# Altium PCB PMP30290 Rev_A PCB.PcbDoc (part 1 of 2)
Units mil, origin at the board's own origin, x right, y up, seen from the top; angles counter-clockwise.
Board outline 2460 x 2050 mil, 4 copper layers (Top Layer, Inner Layer 1, Inner Layer 2, Bottom Layer), stack 84.834 mil thick; 95 components, 59 nets, 283 pads, 121 vias.
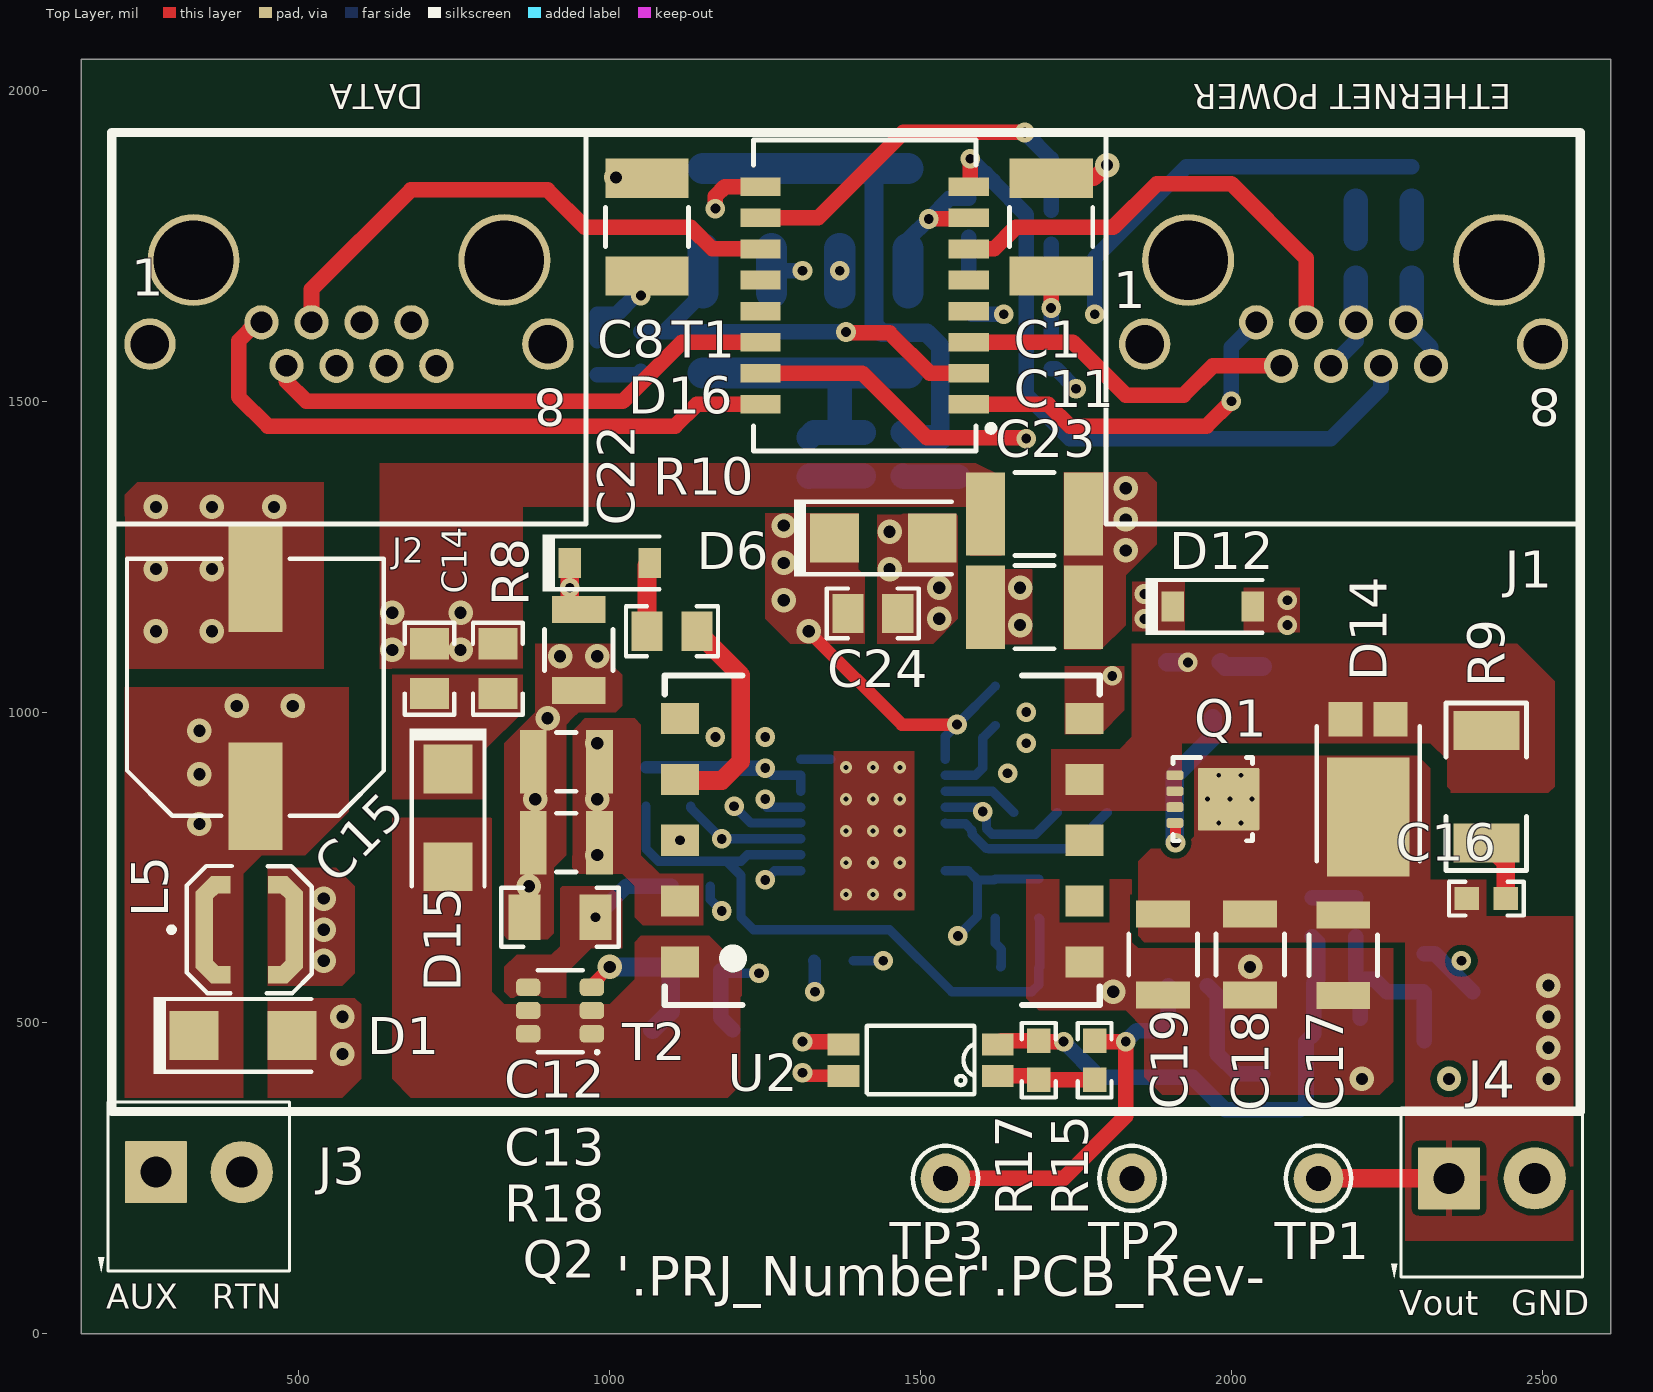
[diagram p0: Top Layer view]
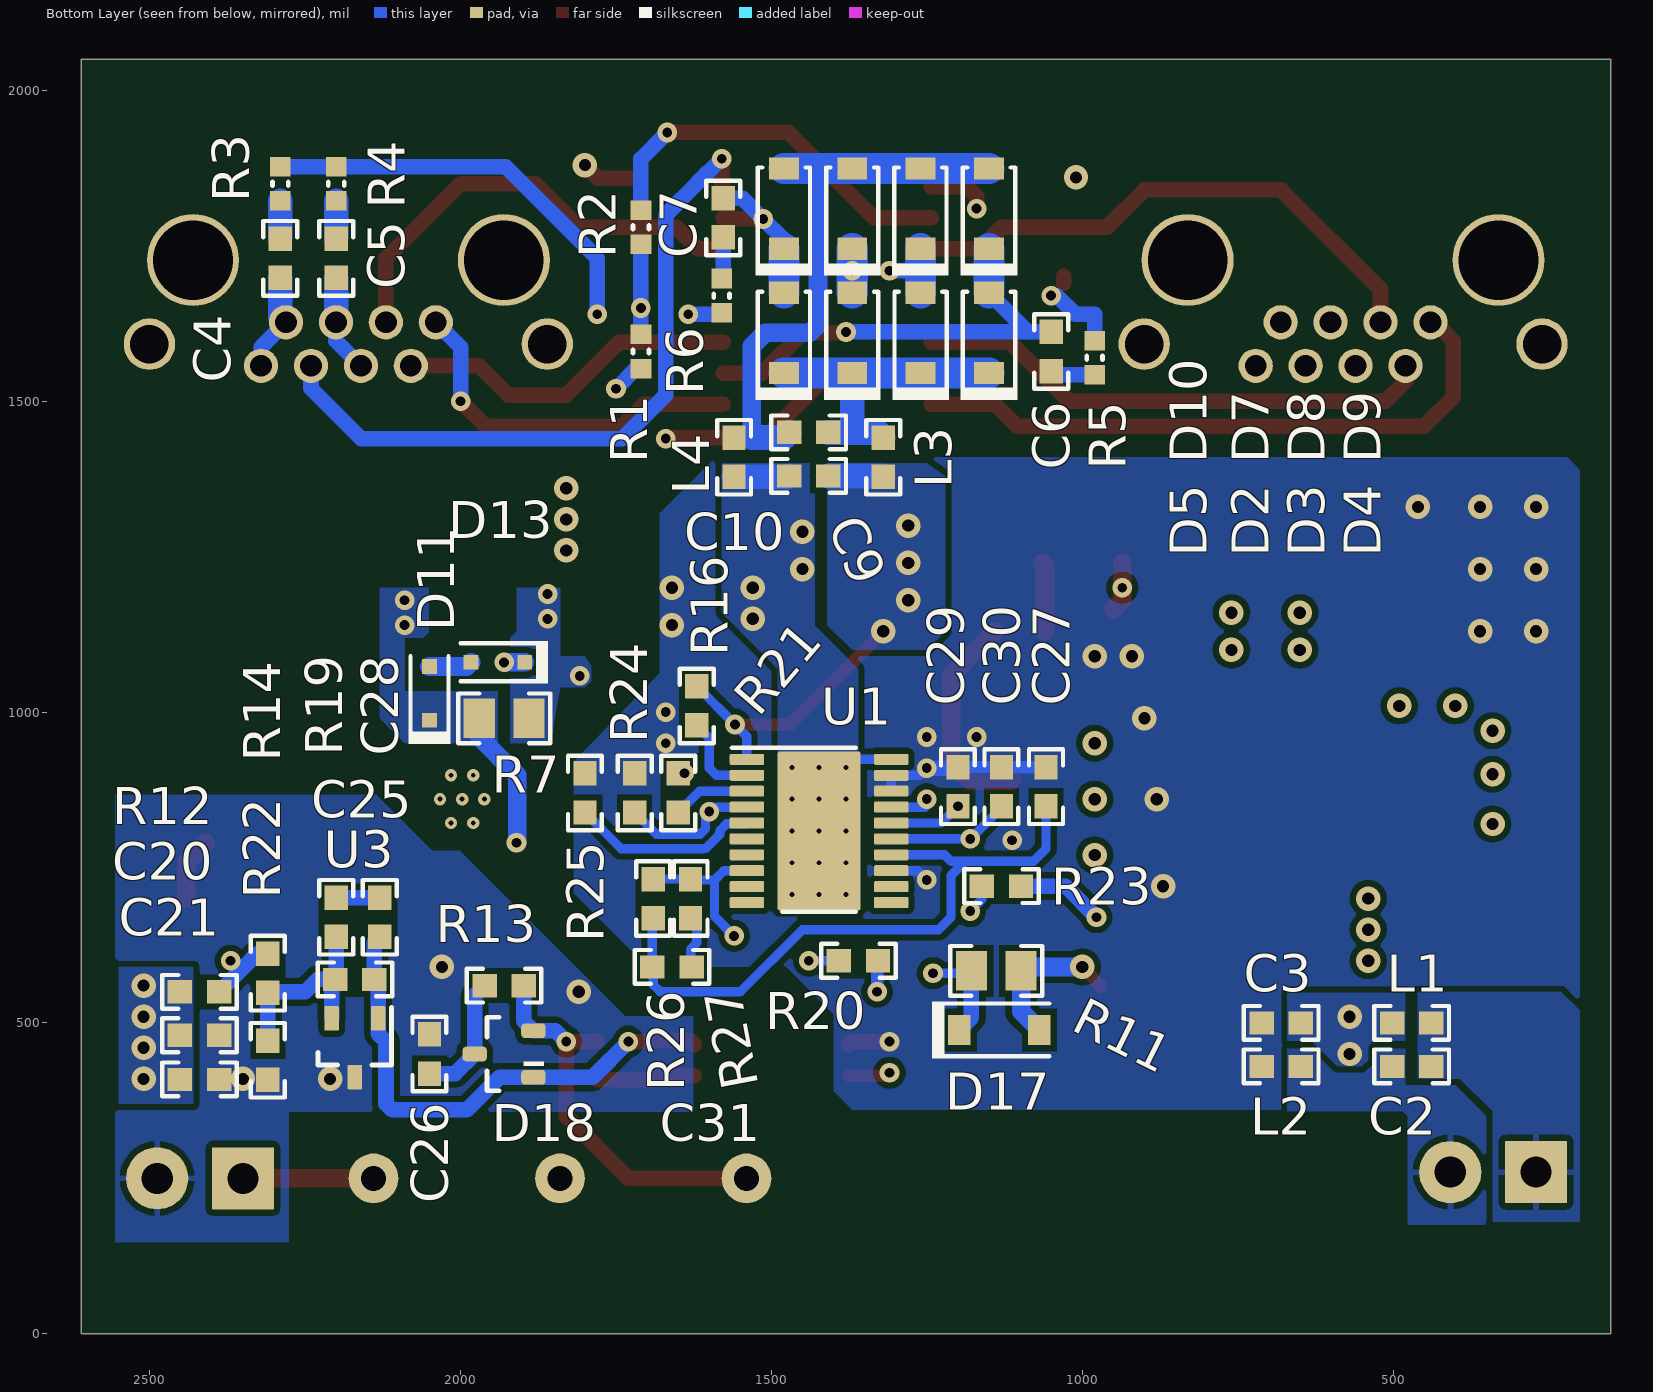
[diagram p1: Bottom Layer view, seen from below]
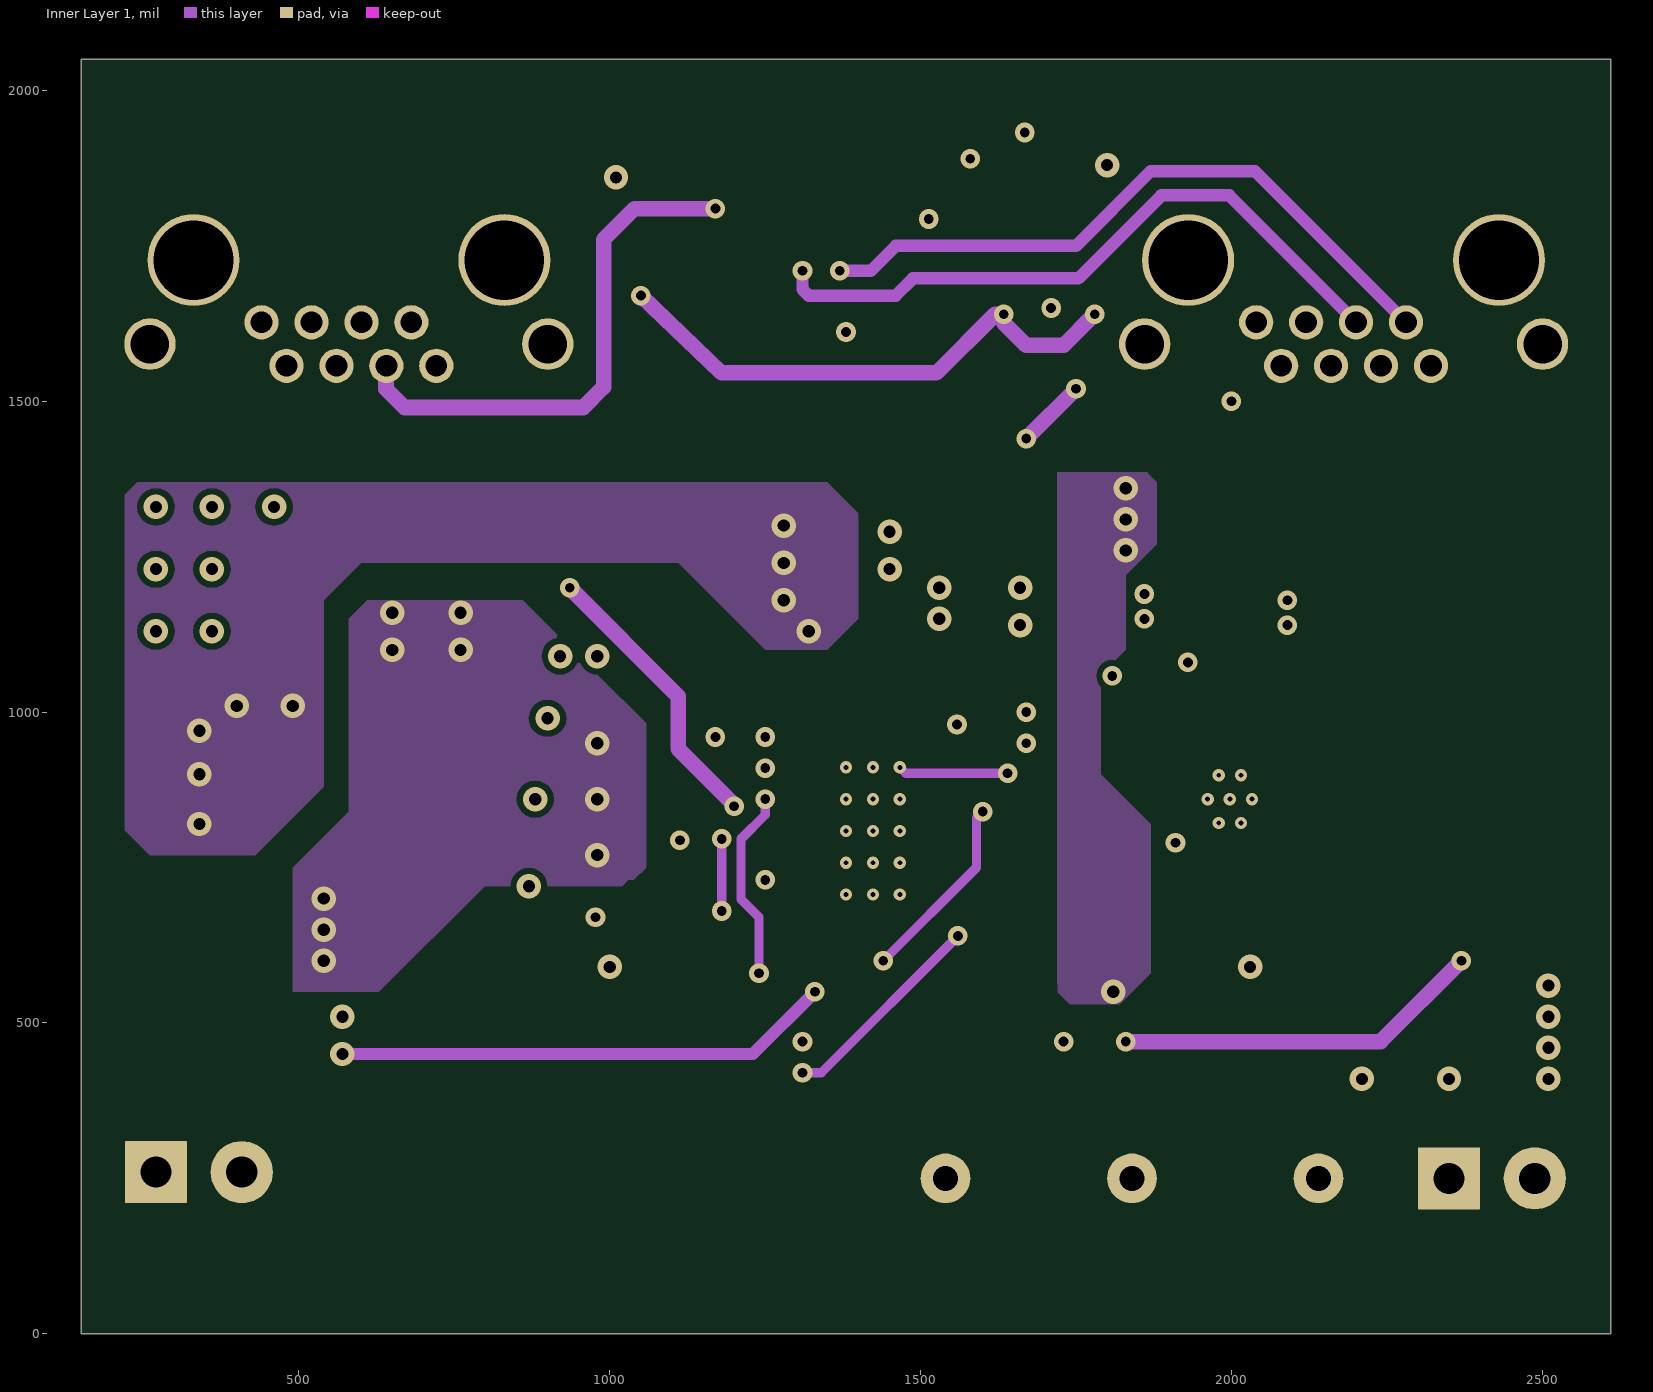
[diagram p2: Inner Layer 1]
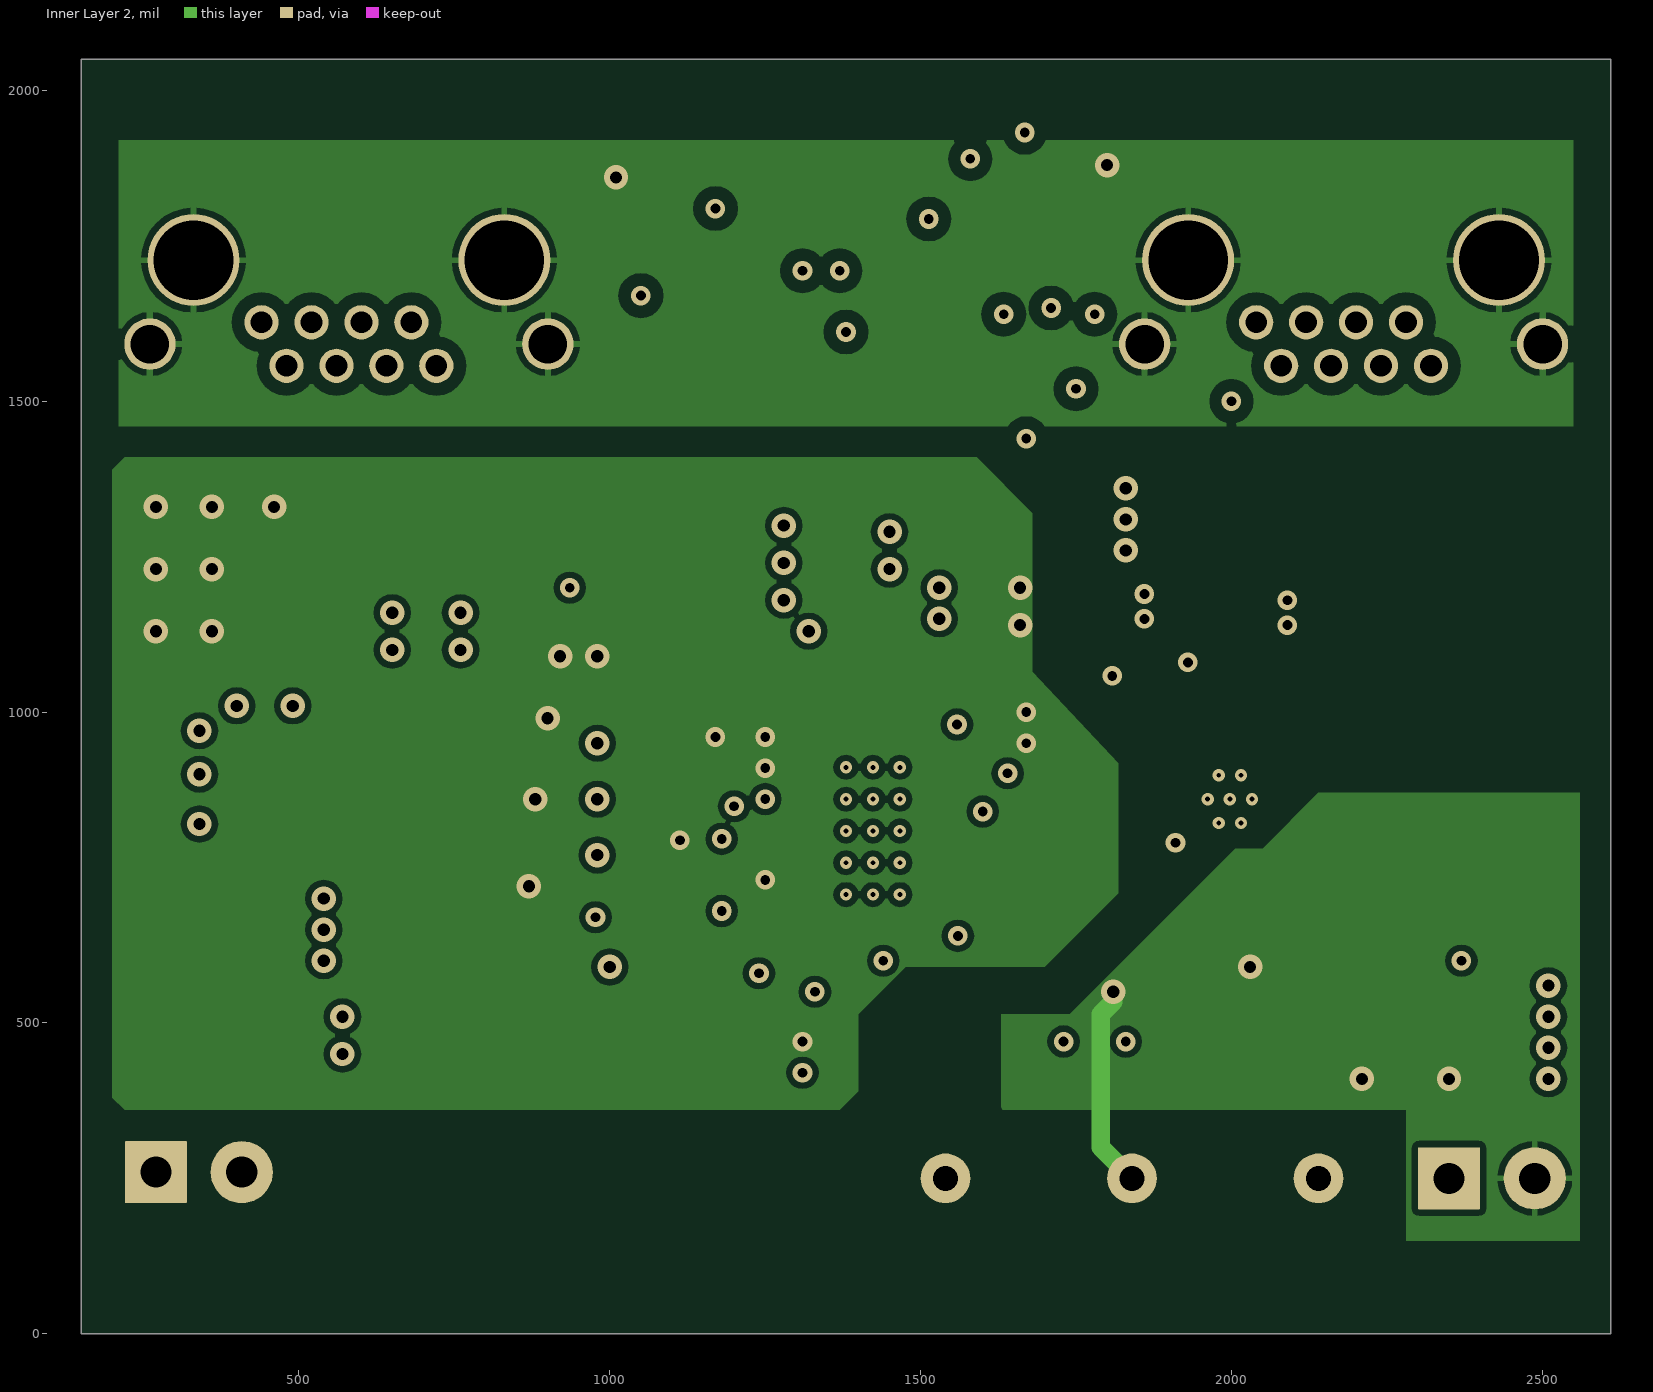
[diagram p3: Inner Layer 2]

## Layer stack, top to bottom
Top Solder: solder mask 0.4, Solder Resist, Dk 3.5
Top Layer: signal copper 1.4
Dielectric 3: dielectric 10, Dk 4.2
Inner Layer 1: signal copper 1.417
Dielectric1: core 59.2, FR-4, Dk 4.8
Inner Layer 2: signal copper 1.417
Dielectric 2: dielectric 10, Dk 4.2
Bottom Layer: signal copper 1.4
Bottom Solder: solder mask 0.4, Solder Resist, Dk 3.5

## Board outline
150,0 150,2050 2610,2050 2610,0

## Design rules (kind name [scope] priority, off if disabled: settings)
AcuteAngle [All] p1: minimum=4.50000000000000E+0001 checktracksonly=FALSE
AssemblyTestPointUsage [All] p1: valid=2
BoardOutlineClearance BoardOutlineClearance_MountingHoles [OnCopper and InComponentClass('Mounting Holes')] p1: gap=40
BoardOutlineClearance BoardOutlineClearance_Poly [OnCopper and IsPoly] p2: gap=25
BoardOutlineClearance [OnCopper and Not InComponentClass('Logo') and not InComponentClass('FiducialMark') and not InRegion(1000,500,4000,800) and not InPoly] p3: gap=75
Clearance "Schematic Clearance Constraint" [InNet('BSP')] p1: gap=20
Clearance Clearance_Keepouts [((IsTrack Or IsArc) And Not InPoly) And IsFree and IsKeepOut vs ((IsTrack Or IsArc) And Not InPoly) And IsFree and IsKeepOut] p2: gap=0
Clearance Clearance_Poly [InPolygon] p3: gap=10
Clearance [All] p4: gap=7.87
ComponentClearance ComponentClearance_MountingHoles_FiducialMarks [InComponentClass('Mounting Holes') vs InComponentClass('FiducialMark')] p1: gap=50 collisioncheckmode=3 verticalgap=10 showdistances=FALSE
ComponentClearance ComponentClearance_Shunt [InComponentClass('Header') vs InComponentClass('Shunt')] p2: gap=0 collisioncheckmode=3 verticalgap=0 showdistances=FALSE
ComponentClearance ComponentClearance_Logo [InComponentClass('Logo')] p3: gap=50 collisioncheckmode=3 verticalgap=10 showdistances=FALSE
ComponentClearance ComponentClearance_ScrewToNut [(HasFootprint('NY PMS 440 0025 PH')) vs (HasFootprint('Keystone_1902C'))] p4: gap=5 collisioncheckmode=3 verticalgap=10 showdistances=FALSE
ComponentClearance ComponentClearance_MountingHoles [InComponentClass('Mounting Holes')] p5: gap=250 collisioncheckmode=3 verticalgap=100000 showdistances=FALSE
ComponentClearance ComponentClearance_SmallPassives [HasFootprint('0201*') or HasFootprint('0402*') or HasFootprint('0508') or HasFootprint('0603*') or HasFootprint('0612') or HasFootprint('0805*') or HasFootprint('0815*') or HasFootprint('0830*') or HasFootprint('1206*') or HasFootprint('1210*') or HasFootprint('1808*') or HasFootprint('1812*') or HasFootprint('1825*') or HasFootprint('2010*') or HasFootprint('2220*') or HasFootprint('2225*') or HasFootprint('2512*') or HasFootprint('2728*') or HasFootprint('3518*') vs HasFootprint('0201*') or HasFootprint('0402*') or HasFootprint('0508') or HasFootprint('0603*') or HasFootprint('0612') or HasFootprint('0805*') or HasFootprint('0815*') or HasFootprint('0830*') or HasFootprint('1206*') or HasFootprint('1210*') or HasFootprint('1808*') or HasFootprint('1812*') or HasFootprint('1825*') or HasFootprint('2010*') or HasFootprint('2220*') or HasFootprint('2225*') or HasFootprint('2512*') or HasFootprint('2728*') or HasFootprint('3518*')] p6: gap=14.96 collisioncheckmode=3 verticalgap=10 showdistances=FALSE
ComponentClearance ComponentClearance_THtoSMT [IsThruComponent vs IsSMTComponent] p7: gap=40 collisioncheckmode=3 verticalgap=30 showdistances=FALSE
ComponentClearance ComponentClearance_THtoTH [IsThruComponent vs IsThruComponent] p8: gap=30 collisioncheckmode=3 verticalgap=30 showdistances=FALSE
ComponentClearance [All] p9: gap=30 collisioncheckmode=3 verticalgap=10 showdistances=FALSE
DiffPairsRouting [All] p1: maxlimit=100 minlimit=10 mostfreqgap=10 toplayer_minwidth=15 toplayer_maxwidth=15 toplayer_prefwidth=15 midlayer1_minwidth=15 midlayer1_maxwidth=15 midlayer1_prefwidth=15 midlayer2_minwidth=15 midlayer2_maxwidth=15 midlayer2_prefwidth=15 bottomlayer_minwidth=15 bottomlayer_maxwidth=15 bottomlayer_prefwidth=15 maxuncoupledlength=1000
FabricationTestPointUsage TestPointUsage [All] p1: valid=2 allowmultiple=FALSE
FabricationTestpoint Testpoint [All] p1: side=3 testpointundercomponent=TRUE minsize=40 maxsize=100 preferedsize=60 minholesize=0 maxholesize=40 preferedholesize=32 testpointgrid=1 allowsidetop=TRUE allowsidebottom=TRUE usegrid=TRUE gridtolerance=0.01
FanoutControl Fanout_LCC [IsLCC] p1: bgadir=Out bgaviamode=Centered fanoutstyle=Auto fanoutdirection=Alternating viagrid=1 // Fanout_LCC (Default Rule)
FanoutControl Fanout_BGA [IsBGA] p2: bgadir=Out bgaviamode=Centered fanoutstyle=Auto fanoutdirection=Alternating viagrid=1 // Fanout_BGA (Default Rule)
FanoutControl Fanout_Default [All] p4: bgadir=Out bgaviamode=Centered fanoutstyle=Auto fanoutdirection=Alternating viagrid=1 // Fanout_Default (Default Rule)
FanoutControl Fanout_Small [(CompPinCount < 5)] p5: bgadir=Out bgaviamode=Centered fanoutstyle=Auto fanoutdirection=OutThenIn viagrid=1 // Fanout_Small (Default Rule)
HoleSize [All] p1: absolutevalues=TRUE maxlimit=251 minlimit=7.87 maxpercent=80.000 minpercent=20.000
MinimumAnnularRing MinimumAnnularRing_ThermalPadVias [IsVia and InAnyComponent] p1: minimumring=5.91
MinimumAnnularRing [All] p2: minimumring=8
MinimumSolderMaskSliver MinimumSolderMaskSliver_Logo [InComponentClass('Logo') vs InComponentClass('Logo')] p1: minsoldermaskwidth=0.7
MinimumSolderMaskSliver [All] p2: minsoldermaskwidth=3.94
PlaneConnect [All] p1: planeconnectstyle=Relief reliefexpansion=10 reliefentries=4 reliefconductorwidth=10 reliefairgap=10
PolygonConnect PolygonConnect_2 [All vs IsSMTPin] p1: connectstyle=Direct reliefconductorwidth=10 reliefentries=4 polygonreliefangle="90 Angle" airgapwidth=10
PolygonConnect PolygonConnect_3 [All vs IsVia] p2: connectstyle=Direct reliefconductorwidth=10 reliefentries=4 polygonreliefangle="90 Angle" airgapwidth=10
PolygonConnect PolygonConnect_1 [All vs IsNamedPolygon('BSP')] p3: connectstyle=Relief reliefconductorwidth=10 reliefentries=4 polygonreliefangle="90 Angle" airgapwidth=10
PolygonConnect [All] p4: connectstyle=Relief reliefconductorwidth=10 reliefentries=4 polygonreliefangle="90 Angle" airgapwidth=10
RoomDefinition "PMP30290 RevA Schematic Page 2" [InComponentClass('PMP30290 RevA Schematic Page 2')] p1: confinementstyle=ConfineIn formatcopy=TRUE lockcomponents=FALSE outline -692,-1534 1308,-1534 1308,-534 -692,-534
RoomDefinition "PMP30290 RevA Schematic Page 1" [InComponentClass('PMP30290 RevA Schematic Page 1')] p2: confinementstyle=ConfineIn formatcopy=TRUE lockcomponents=FALSE outline -692,-1534 1308,-1534 1308,-534 -692,-534
RoutingVias ThermalPadVias [IsVia and InAnyComponent] p1: holewidth=7.87 width=19.68 viastyle="Through Hole" minholewidth=7.87 minwidth=19.68 maxholewidth=12.99 maxwidth=23.62
RoutingVias [All] p2: holewidth=16 width=34 viastyle="Through Hole" minholewidth=7.87 minwidth=26 maxholewidth=40 maxwidth=65 useviatemplates=TRUE viatemplateguid#1={23C83835-86FD-4572-BB9E-8314481B5725} viatemplatename#1=v80h40
SilkToBoardRegionClearance [Not ((IsComment or IsDesignator) And (Hide <> 'False')) and not InRegion(1000,500,4000,800)] p1:
SilkToSilkClearance SilkToSilkClearance_Pb-FreeLogo [(HasFootprint('Pb-Free_Overlay_Medium') OR HasFootprint('Pb-Free_Overlay_Small')) vs (HasFootprint('Pb-Free_Overlay_Medium') OR HasFootprint('Pb-Free_Overlay_Small'))] p1: silktosilkclearance=0
SilkToSilkClearance [All] p2: silktosilkclearance=4
SilkToSolderMaskClearance SilkToComponentPadClearance [(IsPad or IsFill or IsRegion) and InAnycomponent] p1: minsilkscreentomaskgap=5 clearancetoexposedcopper=TRUE
SilkToSolderMaskClearance "Silk to Solder Mask Opening" [All] p2: minsilkscreentomaskgap=4 clearancetoexposedcopper=FALSE
SolderMaskExpansion [All] p1: expansion=1.97
Width [All] p1: maxlimit=100 minlimit=6 preferedwidth=10 checkconnectedcopper=TRUE
15 further rules are at their usual default settings.

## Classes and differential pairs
component class "PMP30290 RevA Schematic Page 1": C1 C2 C3 C4 C5 C6 C7 C8 C9 C10 D1 D2 D3 D4 D5 D6 D7 D8 D9 D10 J1 J2 J3 L1 L2 L3 L4 R1 R2 R3 R4 R5 R6 T1
component class "PMP30290 RevA Schematic Page 2": C11 C12 C13 C14 C15 C16 C17 C18 C19 C20 C21 C22 C23 C24 C25 C26 C27 C28 C29 C30 C31 D11 D12 D13 D14 D15 D16 D17 D18 J4 L5 Q1 Q2 R7 R8 R9 R10 R11 R12 R13 R14 R15 R16 R17 R18 R19 R20 R21 R22 R23 R24 R25 R26 R27 T2 TP1 TP2 TP3 U1 U2 U3

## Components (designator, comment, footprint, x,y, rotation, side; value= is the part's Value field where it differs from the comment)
C1 "1812GC102KA1" 1812_254 1710,1780 r90 top
C2 "C1608X7R2A102K080AA" 0603 470,430 r0 bottom
C3 "C1608X7R2A102K080AA" 0603 680,500 r0 bottom
C4 "C0603C103K1RACTU" 0603 2290,1730 r90 bottom
C5 "C0603C103K1RACTU" 0603 2200,1730 r90 bottom
C6 "C0603C103K1RACTU" 0603 1050,1580 r270 bottom
C7 "C0603C103K1RACTU" 0603 1577.51,1795.01 r270 bottom
C8 "1812GC102KA1" 1812_254 1060,1780 r90 top
C9 "C1608X7R2A102K080AA" 0603 1440,1450 r0 bottom
C10 "C1608X7R2A102K080AA" 0603 1440,1380 r0 bottom
C11 "1812GC102KA1" 1812_254 1683.31,1318.82 r0 top
C12 "GRM32ER72A225KA35L" 1210_270L 930,920 r180 top
C13 "GRM32ER72A225KA35L" 1210_270L 930,790 r180 top
C14 "C2012X7R2A104K125AA" 0805_HV 710,1070 r270 top
C15 "EMVH101ADA220MJA0G" CAPSMT_62_JA0 430,1040 r90 top
C16 "C1608X7R2A102K080AA" 0603 2410,700 r180 top
C17 "C1210C107M8PACTU" 1210_280 2180,608.98 r270 top
C18 "C1210C107M8PACTU" 1210_280 2030,610 r270 top
C19 "C1210C107M8PACTU" 1210_280 1890,610 r270 top
C20 "885012206052" 0603 2420,480 r180 bottom
C21 "885012206046" 0603 2420,408.98 r180 bottom
C22 "12103D226MAT2A" 1210_280 950,1100 r270 top
C23 "1812GC102KA1" 1812_254 1683.31,1168.82 r0 top
C24 "C2012X7R2A104K125AA" 0805_HV 1423.31,1158.82 r0 top
C25 "GRM1885C1H471JA01D" 0603 2170,570 r180 bottom
C26 "885012206052" 0603 2050,450 r90 bottom
C27 "GRM188R71C474KA88D" 0603 1058.31,880 r270 bottom
C28 "GRM188R71H683KA93D" 0603 2130,670 r270 bottom
C29 "885012206052" 0603 1200,880 r90 bottom
C30 "GRM1885C1H221JA01D" 0603 1130,880 r90 bottom
C31 "C0603X223K5RACTU" 0603 1660,590 r180 bottom
D1 "B1100-13-F" SMA 410,480 r0 top
D2 "MBR1H100SFT3G" SOD-123FL 1370,1610 r90 bottom
D3 "MBR1H100SFT3G" SOD-123FL 1260,1610 r90 bottom
D4 "MBR1H100SFT3G" SOD-123FL 1150,1610 r90 bottom
D5 "MBR1H100SFT3G" SOD-123FL 1480,1610 r90 bottom
D6 "SMAJ58A-13-F" SMA 1440,1280 r0 top
D7 "MBR1H100SFT3G" SOD-123FL 1370,1810 r90 bottom
D8 "MBR1H100SFT3G" SOD-123FL 1260.39,1810 r90 bottom
D9 "MBR1H100SFT3G" SOD-123FL 1150,1810 r90 bottom
D10 "MBR1H100SFT3G" SOD-123FL 1480,1810 r90 bottom
D11 "MMSZ5245BS-7-F" SOD-323 2050,1030 r90 bottom
D12 "MBR0530T1G" SOD-123 1970,1170 r0 top
D13 "MMSZ5245BS-7-F" SOD-323 1940,1080 r0 bottom
D14 "PDS360-13" PowerDI5 2220,910 r270 top
D15 "MURA120T3G" SMA 740,830 r270 top
D16 "MMSD4148T1G" SOD-123 1000,1240 r0 top
D17 "MBR0530T1G" SOD-123 1133.31,488.82 r180 bottom
D18 "BAT54S-7-F" SOT-23 1930,450 r0 bottom
J1 "1-406541-1" TEC_1-406541-1 2180,1620 r180 top
J2 "1-406541-1" TEC_1-406541-1 580,1620 r180 top
J3 "ED555/2DS" TERM_BLK_ED555-2DS 270,260 r0 top
J4 "ED555/2DS" TERM_BLK_ED555-2DS 2350,250 r0 top
L1 "MPZ1608S221A" 0603 470,500 r0 bottom
L2 "MPZ1608S221A" 0603 680,430 r0 bottom
L3 "MPZ1608S221A" 0603 1320,1410 r270 bottom
L4 "MPZ1608S221A" 0603 1560,1410 r270 bottom
L5 "LPS4018-103MRB" LPS4018 420,650 r0 top
Q1 "CSD17551Q3A" DNH0008A 1970,860 r0 top
Q2 "FDC86244" SOT-6 920,520 r180 top
R1 "CRCW060375R0FKEA" 0603L 1710,1580 r270 bottom
R2 "CRCW060375R0FKEA" 0603L 1710,1780 r90 bottom
R3 "CRCW060375R0FKEA" 0603L 2290,1850 r270 bottom
R4 "CRCW060375R0FKEA" 0603L 2200,1850 r270 bottom
R5 "CRCW060375R0FKEA" 0603L 980,1570 r270 bottom
R6 "CRCW060375R0FKEA" 0603L 1580,1670 r90 bottom
R7 "CRCW080510R0JNEA" 0805_HV 1930,990 r0 bottom
R8 "CRCW080539K0JNEA" 0805_HV 820,1070 r90 top
R9 "CRCW201010R0FKEF" 2010 2410,880 r270 top
R10 "CRCW080510R0JNEA" 0805_HV 1100,1130 r0 top
R11 "CRCW080510R0JNEA" 0805_HV 1138.31,583.82 r180 bottom
R12 "RC0603FR-0749R9L" 0603 2420,550 r0 bottom
R13 "RC0603FR-0710KL" 0603 1930,560 r180 bottom
R14 "RC0603FR-0710KL" 0603 2310,580 r90 bottom
R15 "RC0603FR-07681RL" 0603 1780,440 r90 top
R16 "RC0603FR-0724K9L" 0603 1620,1010 r90 bottom
R17 "RC0603FR-072K21L" 0603 1690,440 r270 top
R18 "ERJ-8BSFR15V" 1206 920,670 r0 top
R19 "RC0603FR-0710KL" 0603 2200,670 r90 bottom
R20 "RC0603FR-07100KL" 0603 1360,600 r180 bottom
R21 "RC0603FR-0790R9L" 0603 1650,870 r270 bottom
R22 "RC0603FR-078K87L" 0603 2310,440 r90 bottom
R23 "RC0603FR-07332RL" 0603 1130,720 r180 bottom
R24 "RC0603FR-079K09L" 0603 1720,870 r270 bottom
R25 "RC0603FR-0734KL" 0603 1800,870 r270 bottom
R26 "RC0603FR-073K65L" 0603 1690,700 r270 bottom
R27 "RC0603FR-071K5L" 0603 1630,700 r270 bottom
T1 "H2019FNLT" PULSE_H2019FNL 1410,1670 r180 top
T2 "NA6223-AL" XFMR_COILCRAFT-699x500x530 1438.31,793.82 r90 top
TP1 "5000" Keystone5000 2140,250 r0 top
TP2 "5001" Keystone5001 1840,250 r90 top
TP3 "5002" Keystone5002 1540,250 r90 top
U1 "TPS23752PWP" PWP0020D_N 1423.31,808.82 r180 bottom
U2 "TCMT1107" SOP-4 1500,440 r180 top
U3 "TL431AIDBZRG4" DBZ0003A_N 2170,460 r270 bottom

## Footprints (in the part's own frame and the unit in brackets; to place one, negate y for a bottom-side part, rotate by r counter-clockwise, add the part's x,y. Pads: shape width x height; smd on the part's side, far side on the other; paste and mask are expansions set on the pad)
0603 [mm] "0603 from SM-752 data"
  rect 1x0.95 smd: 1(-0.8,0) 2(0.8,0)
  silkscreen extent -1.52,-0.69 1.52,0.69, body extent -0.87,-0.47 0.87,0.47, height 1
0603L [mm] "0603 from SM-752 data"
  rect 0.8x0.85 smd: 1(-0.7,0) 2(0.7,0)
  silkscreen extent -0.07,-0.33 0.07,0.33, body extent -0.87,-0.47 0.87,0.47, height 1
0805_HV [mil] "0805 with 30mil clearance between pads"
  rect 50x63 smd: 1(-40,0) 2(40,0)
  silkscreen extent -74,-40 74,40, body extent -43,-29 43,29, height 57
1206 [mm] "1206 from SM-752 data"
  rect 1.3x1.85 smd: 1(-1.45,0) 2(1.45,0)
  silkscreen extent -2.4,-1.21 2.4,1.21, body extent -1.7,-0.9 1.7,0.9, height 1.35
1210_270L [mm] "1210"
  rect 1.1x2.6 smd: 1(-1.35,0) 2(1.35,0)
  silkscreen extent -0.4,-1.2 0.4,1.2, body extent -1.7,-1.35 1.7,1.35, height 2.7
1210_280 [mm] "SMD, 2-Leads, Body 3.6x2.8mm, Height 2.8mm"
  rect 1.1x2.2 smd: 1(-1.65,0) 2(1.65,0)
  silkscreen extent -0.84,-1.4 0.84,1.4, body extent -1.8,-1.4 1.8,1.4, height 2.8
1812_254 [mm] "SMD, 2-Leads, Body 4.8x3.4mm"
  rect 1.6x3.4 smd: 1(-2,0) 2(2,0)
  silkscreen extent -0.8,-1.7 0.8,1.7, body extent -2.4,-1.7 2.4,1.7, height 2.54
2010 [mm] "Chip Capacitor, Body 5.08x2.54mm, IPC Medium Density"
  rect 1.6x2.7 smd: 1(-2.3,0) 2(2.3,0)
  silkscreen extent -3.42,-1.65 3.42,1.65, body extent -2.73,-1.45 2.73,1.45, height 1.66
CAPSMT_62_JA0 [mm] "10 x 10mm:  Chemi-Con JA0"
  rect 4.4x2.2 smd: 1(-4.45,0) 2(4.45,0)
  silkscreen extent -5.25,-5.25 5.25,5.25, body extent -5.25,-5.25 5.25,5.25, height 10.5
DBZ0003A_N [mm] "SOT23, 3-Leads, Body 2.9x1.3mm, Pitch 0.95mm, Lead Span 2.4mm, IPC Medium Density"
  rrect17% 1x0.6 smd: 1(-1.2,0.95) 2(-1.2,-0.95) 3(1.2,0)
  silkscreen extent -1.65,-1.5 0.7,1.5, body extent -1.26,-1.46 1.26,1.46, height 0.98
DNH0008A [mm] "8 pin VSONP, 0.65 mm pitch"
  rrect50% 0.7x0.4 smd paste-0.05 mask-0.05: 1(-1.55,0.975) 2(-1.55,0.325) 3(-1.55,-0.325) 4(-1.55,-0.975) 5(1.55,-0.975) 6(1.55,-0.325) 7(1.55,0.325) 8(1.55,0.975)
  rrect14% 0.705x1.125 on Top Paste: 9(-0.208,-0.663) 9(-0.208,0.662) 9(0.697,-0.663) 9(0.697,0.662)
  rrect6% 1.775x2.45 on Top Solder: 9(0.327,0)
  rrect4% 2.51x2.55 smd paste-1.5 mask-1.5: 9(0.645,0)
  rect 0.5x0.3 on Top Solder: 9(1.175,-0.975) 9(1.175,-0.325) 9(1.175,0.325) 9(1.175,0.975)
  silkscreen extent -1.62,-1.7 1.62,1.7, body extent -1.65,-1.65 1.65,1.66, height 0.91
Keystone5000 [mil] "For Keystone 500x miniature loop terminals"
  round 80 hole 40: 1(0,0)
  silkscreen extent -52,-52 52,52, body extent -49,-49 49,49, height 182
Keystone5001 [mil] "For Keystone 500x miniature loop terminals"
  round 80 hole 40: 1(0,0)
  silkscreen extent -52,-52 52,52, body extent -49,-49 49,49, height 182
Keystone5002 [mil] "For Keystone 500x miniature loop terminals"
  round 80 hole 40: 1(0,0)
  silkscreen extent -52,-52 52,52, body extent -49,-49 49,49, height 182
LPS4018 [mil]
  rect 28x123 smd: 1(-72.5,0) 2(72.5,0)
  rect 35.5x28 smd rot 135: 1(-64,-64) 2(64,64)
  rect 35.5x28 smd rot 45: 1(-64,64) 2(64.5,-63.5)
  rect 31.5x28 smd: 1(-46,-72.5) 1(-46,72.5) 2(46,-72.5) 2(46,72.5)
  silkscreen extent -129,-102 100,102, body extent -81,-81 81,81, height 71
PowerDI5 [mm] "Diodes Inc recommended land pattern, ap02001.pdf rev 60"
  rect 1.4x1.39 smd: 1(-1.991,0.92) 2(-1.991,-0.92)
  rect 4.86x3.36 smd: 3(1.991,0)
  silkscreen extent -1.7,-2.1 3.8,2.1, body extent -2.27,-2.03 4.33,2.03, height 1.17
PULSE_H2019FNL [mil] "PULSE"
  rect 65x30 smd paste+0: 1(-167.51,174.99) 2(-167.51,124.99) 3(-167.51,74.99) 4(-167.51,24.99) 5(-167.51,-25.01) 6(-167.51,-75.01) 7(-167.51,-125.01) 8(-167.51,-175.01) 9(167.49,-175.01) 10(167.49,-125.01) 11(167.49,-75.01) 12(167.49,-25.01) 13(167.49,24.99) 14(167.49,74.99) 15(167.49,124.99) 16(167.49,174.99)
  silkscreen extent -208,-250 179,250, body extent -179,-250 179,250, height 236
PWP0020D_N [mm] "SOP, 20-Leads, Body 6.4x4.4mm, Pitch 0.65mm, Thermal Pad 2x3mm, IPC Medium Density"
  rrect22% 1.4x0.45 smd: 1(-2.95,2.925) 2(-2.95,2.275) 3(-2.95,1.625) 4(-2.95,0.975) 5(-2.95,0.325) 6(-2.95,-0.325) 7(-2.95,-0.975) 8(-2.95,-1.625) 9(-2.95,-2.275) 10(-2.95,-2.925) 11(2.95,-2.925) 12(2.95,-2.275) 13(2.95,-1.625) 14(2.95,-0.975) 15(2.95,-0.325) 16(2.95,0.325) 17(2.95,0.975) 18(2.95,1.625) 19(2.95,2.275) 20(2.95,2.925)
  rrect6% 3.4x6.5 smd paste-2 mask-2: 21(0,0)
  rrect4% 2.4x3.7 on Bottom Paste: 21(0,0)
  rrect4% 2.4x3.7 on Bottom Solder: 21(0,0)
  silkscreen extent -3.55,-3.3 1.5,3.4, body extent -3.21,-3.25 3.21,3.25, height 1
SMA [mm] "Molded Diode, 2-Leads, Body 4.3x2.6mm, IPC Medium Density, based on OnSemi component dimensions and land pattern"
  rect 2x2 smd: 1(-2,0) 2(2,0)
  silkscreen extent -3.66,-1.57 2.79,1.57, body extent -2.6,-1.3 2.6,1.3, height 2.42
SOD-123 [mm] "On Semi recommended land pattern"
  rect 0.915x1.22 smd: 1(-1.637,0) 2(1.637,0)
  silkscreen extent -2.74,-1.17 2.03,1.17, body extent -1.93,-0.9 1.93,0.9, height 1.35
SOD-123FL [mm] "Copied from SOD-123"
  rect 0.915x1.22 smd: 1(-1.637,0) 2(1.637,0)
  silkscreen extent -2.74,-1.16 1.68,1.16, body extent -1.9,-0.9 1.9,0.9, height 1
SOD-323 [mm] "NXP recommended land pattern"
  rect 0.6x0.6 smd paste-0.05: 1(-1.1,0) 2(1.1,0)
  silkscreen extent -2.06,-0.86 1.53,0.86, body extent -1.3,-0.67 1.3,0.68, height 1.1
SOP-4 [mm] "Vishay Half Pitch Mini-Flat Package"
  rect 1.3x0.9 smd: 1(-3.15,0.635) 2(-3.15,-0.635) 3(3.15,-0.635) 4(3.15,0.635)
  silkscreen extent -2.2,-1.41 2.2,1.39, body extent -3.5,-1.4 3.5,1.4, height 2.12
SOT-6 [mm] "Fairchild recommended land pattern for SuperSOT-6 in MA06A.pdf dated 17OCT2005"
  rrect50% 1x0.7 smd: 1(-1.3,0.95) 2(-1.3,0) 3(-1.3,-0.95) 4(1.3,-0.95) 5(1.3,0) 6(1.3,0.95)
  silkscreen extent -1.52,-1.64 0.9,1.71, body extent -1.43,-1.48 1.43,1.49, height 0.9
SOT-23 [mm] "SOT23, 3-Leads, Body 2.9x1.3mm, Pitch 0.95mm, Lead Span 2.5mm, IPC Medium Density"
  rrect50% 1x0.6 smd: 1(-1.2,0.95) 2(-1.2,-0.95) 3(1.2,0)
  silkscreen extent -1.63,-1.5 0.7,1.5, body extent -1.16,-1.45 1.21,1.45, height 1
TEC_1-406541-1 [mm] "TE Connectivity"
  round 1.4 hole 0.89: 1(3.56,-0.18) 2(2.54,1.6) 3(1.52,-0.18) 4(0.5,1.6) 5(-0.52,-0.18) 6(-1.54,1.6) 7(-2.56,-0.18) 8(-3.58,1.6)
  round 2.1 hole 1.57: 9(8.12,0.71) 10(-8.14,0.71)
  round 3.759 hole 3.251: 11(6.34,-2.72) 12(-6.36,-2.72)
  silkscreen extent -9.69,-8 9.69,8.06, body extent -9.33,-8 9.31,7.75, height 14.8
TERM_BLK_ED555-2DS [mil]
  rrect4% 100x100 hole 50: 1(0,0)
  round 100 hole 50: 2(138,0)
  silkscreen extent -93,-161 215,113, body extent -69,-150 207,106, height 323
XFMR_COILCRAFT-699x500x530 [mil] "Coilcraft Transformer"
  rect 50x61 smd: 1(-196,325.5) 2(-98,325.5) 3(0,325.5) 4(98,325.5) 5(196,325.5) 6(196,-325.5) 7(98,-325.5) 8(0,-325.5) 9(-98,-325.5) 10(-196,-325.5)
  silkscreen extent -265,-350 265,350, body extent -266,-276 265,279, height 504

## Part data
C1 C8 C11 C23: "CAP, CERM, 1000 pF, 2000 V, +/- 10%, X7R, 1812"
C2 C3 C9 C10 C16: "CAP, CERM, 1000 pF, 100 V, +/- 10%, X7R, 0603"
C4 C5 C6 C7: "CAP, CERM, 0.01 µF, 100 V, +/- 10%, X7R, 0603"
C12 C13: "CAP, CERM, 2.2 µF, 100 V, +/- 10%, X7R, 1210"
C14 C24: "CAP, CERM, 0.1 µF, 100 V, +/- 10%, X7R, 0805"
C15: "CAP, AL, 22 µF, 100 V, +/- 20%, 0.55 ohm, SMD"
C17 C18 C19: "CAP, CERM, 100 µF, 10 V, +/- 20%, X5R, 1210"
C20 C26 C29: "CAP, CERM, 1 µF, 16 V, +/- 10%, X7R, 0603"
C21: "CAP, CERM, 0.1 µF, 16 V, +/- 10%, X7R, 0603"
C22: "CAP, CERM, 22 µF, 25 V, +/- 20%, X5R, 1210"
C25: "CAP, CERM, 470 pF, 50 V, +/- 5%, C0G/NP0, 0603"
C27: "CAP, CERM, 0.47 µF, 16 V, +/- 10%, X7R, 0603"
C28: "CAP, CERM, 0.068 µF, 50 V, +/- 10%, X7R, 0603"
C30: "CAP, CERM, 220 pF, 50 V, +/- 5%, C0G/NP0, 0603"
C31: "CAP, CERM, 0.022 µF, 50 V, +/- 10%, X7R, 0603"
D1: "Diode, Schottky, 100 V, 1 A, SMA"
D2 D3 D4 D5 D7 D8 D9 D10: "Diode, Schottky, 100 V, 1 A, SOD-123FL"
D6: "Diode, TVS, Uni, 58 V, SMA"
D11 D13: "Diode, Zener, 15 V, 200 mW, SOD-323"
D12 D17: "Diode, Schottky, 30 V, 0.5 A, SOD-123"
D14: "Diode, Schottky, 60 V, 3 A, PowerDI5"
D15: "Diode, Ultrafast, 200 V, 1 A, SMA"
D16: "Diode, Switching, 100 V, 0.2 A, SOD-123"
D18: "Diode, Schottky, 30 V, 0.2 A, SOT-23"
J1 J2: "RJ-45, Right Angle, No LED, tab up"
J3 J4: "Terminal Block, 3.5mm Pitch, 2x1, TH"
L1 L2 L3 L4: "Ferrite Bead, 220 ohm @ 100 MHz, 2.2 A, 0603"
L5: "Inductor, Shielded Drum Core, Ferrite, 10 µH, 1.25 A, 0.18 ohm, SMD"
Q1: "MOSFET, N-CH, 30 V, 12 A, DNH0008A (VSONP-8)"
Q2: "MOSFET, N-CH, 150 V, 2.3 A, SuperSOT-6"
R1 R2 R3 R4 R5 R6: "RES, 75.0, 1%, 0.1 W, 0603"
R7 R10 R11: "RES, 10, 5%, 0.125 W, 0805"
R8: "RES, 39 k, 5%, 0.125 W, 0805"
R9: "RES, 10.0, 1%, 0.75 W, AEC-Q200 Grade 0, 2010"
R12: "RES, 49.9, 1%, 0.1 W, 0603"
R13 R14 R19: "RES, 10.0 k, 1%, 0.1 W, 0603"
R15: "RES, 681, 1%, 0.1 W, 0603"
R16: "RES, 24.9 k, 1%, 0.1 W, 0603"
R17: "RES, 2.21 k, 1%, 0.1 W, 0603"
R18: "RES, 0.15, 1%, 0.5 W, 1206"
R20: "RES, 100 k, 1%, 0.1 W, 0603"
R21: "RES, 90.9, 1%, 0.1 W, 0603"
R22: "RES, 8.87 k, 1%, 0.1 W, 0603"
R23: "RES, 332, 1%, 0.1 W, 0603"
R24: "RES, 9.09 k, 1%, 0.1 W, 0603"
R25: "RES, 34.0 k, 1%, 0.1 W, 0603"
R26: "RES, 3.65 k, 1%, 0.1 W, 0603"
R27: "RES, 1.50 k, 1%, 0.1 W, 0603"
T1: "Transformer, 350uH, SMT"
T2: "Transformer, Flyback, 198 uH"
TP1: "Test Point, Miniature, Red, TH"
TP2: "Test Point, Miniature, Black, TH"
TP3: "Test Point, Miniature, White, TH"
U1: "IEEE 802.3at PoE Interface and Green-mode DC/DC Controller, PWP0020D (TSSOP-20)"
U2: "Optocoupler, 3.75 kV, 80-160% CTR, SMT"
U3: "Adjustable Precision Shunt Regulator, 34 ppm / degC, 100 mA, -40 to 85 degC, 3-pin SOT-23 (DBZ), Green (RoHS & no Sb/Br)"

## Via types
v1: diameter 39.37, hole 19.68, Top Layer to Bottom Layer, 53 vias
v2: diameter 31.5, hole 15.75, Top Layer to Bottom Layer, 46 vias
v3: diameter 19.68, hole 7.87, Top Layer to Bottom Layer, 16 vias
v4: diameter 19.68, hole 7.87, Top Layer to Bottom Layer, tented both sides, 6 vias

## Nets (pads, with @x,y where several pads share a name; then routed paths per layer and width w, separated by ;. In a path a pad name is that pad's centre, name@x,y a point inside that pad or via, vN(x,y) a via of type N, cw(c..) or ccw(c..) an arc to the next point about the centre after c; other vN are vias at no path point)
AUX: C3.1 D1.2 L1.2 R20.2 | length 852
  Inner Layer 1 w20: v1(570,450) 1230,450 v2(1330,550)
  Bottom Layer w20: R20.2@1328.5,600 1330,598.5 v2(1330,550)
  other v1: 570,510
BSP: C1.2 C8.2 J1.9 J1.10 J1.11 J1.12 J2.9 J2.10 J2.11 J2.12 | length 98.8
  Top Layer w25: C1.2@1710,1858.74 1778.74,1858.74 v1(1800,1880)
  other v1: 1010,1860
GND: C11.2 C17.2 C18.2 C19.2 C20.2 C21.2 C23.2 C26.2 J4.2 R22.1 T2.10 TP2.1 U3.3 | length 329
  Inner Layer 2 w30: v1(1810,550) 1810,533.82 1790,513.82 1790,300 TP2.1@1840,250
  other v1: 2210,410 2350,410 2030,590 1830,1260 1830,1310 1830,1360
NetC1_1: C1.1 R1.1 R2.1 | length 196.1
  Top Layer w25: v2(1710,1650) C1.1@1710,1701.26
  Bottom Layer w25: R1.1@1710,1607.56 v2(1710,1650) R2.1@1710,1752.44
NetC2_1: C2.1 J3.1 L1.1
NetC2_2: C2.2 J3.2 L2.1
NetC4_1: C4.1 D2.2 D7.1 J1.7 J1.8 | length 1310.7
  Inner Layer 1 w20: v2(1370,1710) 1420,1710 1460,1750 1750,1750 1870,1870 2037.87,1870 J1.7@2280.79,1627.09
  Bottom Layer w25: J1.7@2280.79,1627.09 2320.94,1586.93 J1.8@2320.94,1557.01
  Bottom Layer w40: J1.7@2280.79,1627.09 2290,1636.3 C4.1@2290,1698.5
  Bottom Layer w50: D2.2@1370,1674.47 v2(1370,1710) D7.1@1370,1745.53
NetC4_2: C4.2 R3.2 | length 60.9
  Bottom Layer w40: C4.2@2290,1761.5 R3.2@2290,1822.44
NetC5_1: C5.1 D3.2 D8.1 J1.4 J1.5 | length 1355.5
  Inner Layer 1 w20: v2(1310,1710) 1310,1680 1320,1670 1460,1670 1487.56,1697.56 1753.79,1697.56 1887.32,1831.09 1996.47,1831.09 J1.5@2200.47,1627.09
  Bottom Layer w25: 1260,1709.8 1260.2,1710 v2(1310,1710) ; J1.4@2160.32,1557.01 2200.47,1597.17 J1.5@2200.47,1627.09
  Bottom Layer w40: C5.1@2200,1698.5 2200,1627.56 J1.5@2200.47,1627.09
  Bottom Layer w50: D3.2@1260,1674.47 1260,1709.8 1260,1745.14 D8.1@1260.39,1745.53
NetC5_2: C5.2 R4.2 | length 60.9
  Bottom Layer w40: C5.2@2200,1761.5 R4.2@2200,1822.44
NetC6_1: C6.1 D4.2 D9.1 T1.2 | length 715.2
  Top Layer w25: v2(1380,1611.5) 1381.5,1610 1450,1610 1514.99,1545.01 T1.2@1577.51,1545.01
  Bottom Layer w25: C6.1@1050,1611.5 1087.03,1611.5 ; D4.2@1150,1674.47 1087.03,1611.5 ; v2(1380,1611.5) 1087.03,1611.5
  Bottom Layer w50: D4.2@1150,1674.47 D9.1@1150,1745.53
NetC6_2: C6.2 R5.2 | length 72.5
  Bottom Layer w25: R5.2@980,1542.44 1043.94,1542.44 C6.2@1050,1548.5
NetC7_1: C7.1 D5.2 D10.1 T1.7 | length 275.6
  Top Layer w25: v2(1513.25,1793.25) 1575.76,1793.25 T1.7@1577.51,1795.01
  Bottom Layer w25: D10.1@1480,1745.53 1480,1760 v2(1513.25,1793.25) 1546.5,1826.5 C7.1@1577.51,1826.5
  Bottom Layer w50: D5.2@1480,1674.47 D10.1@1480,1745.53
NetC7_2: C7.2 R6.2 | length 67
  Bottom Layer w25: C7.2@1577.51,1763.51 1577.51,1700.05 R6.2@1580,1697.56
NetC8_1: C8.1 R3.1 R4.1 R5.1 R6.1 | length 1720.4
  Top Layer w25: C8.1@1030,1690 C8.1@1030,1701.26
  Inner Layer 1 w25: v2(1050,1670) 1180,1545.53 1525.53,1545.53 1620,1640 v2(1633.63,1640) 1633.63,1626.37 1670,1590 1730,1590 v2(1780,1640)
  Bottom Layer w25: R5.1@980,1597.56 980,1640 1011.3,1640 1041.3,1670 v2(1050,1670) ; R6.1@1580,1642.44 1582.44,1640 v2(1633.63,1640) ; v2(1780,1640) 1780,1730 1927.56,1877.56 R4.1@2200,1877.56 R3.1@2290,1877.56
NetC9_1: C9.1 D2.1 D3.1 D4.1 D5.1 L3.1 | length 517.6
  Bottom Layer w40: L3.1@1320,1441.5 1328.5,1450 C9.1@1408.5,1450 ; 1370,1450 D2.1@1370,1545.53
  Bottom Layer w50: D4.1@1150,1545.53 D3.1@1260,1545.53 D2.1@1370,1545.53 D5.1@1480,1545.53
NetC9_2: C9.2 D7.2 D8.2 D9.2 D10.2 L4.1 | length 912.7
  Bottom Layer w30: 1425,1874.47 1425,1623 1438,1610 1510,1610 1531.46,1588.54 1531.46,1441.5
  Bottom Layer w40: C9.2@1471.5,1450 1480,1441.5 1531.46,1441.5
  Bottom Layer w50: D9.2@1150,1874.47 D8.2@1260.39,1874.47 D7.2@1370,1874.47 1425,1874.47 D10.2@1480,1874.47
NetC11_1: C11.1 C12.1 C13.1 C14.1 L5.2 R8.2 T2.2
  other v1: 540,600 540,650 540,700 980,770 980,860 980,950 650,1100 760,1100 650,1160 760,1160
NetC14_2: C14.2 D15.1 R8.1
NetC16_1: C16.1 R9.2 | length 102.5
  Top Layer w30: R9.2@2410,789.45 2441.5,757.95 C16.1@2441.5,700
NetC22_1: C22.1 C29.1 D16.1 U1.16 | length 660.4
  Top Layer w30: D16.1@935.53,1240 v2(935.53,1200) 935.53,1179.43 C22.1@950,1164.96
  Inner Layer 1 w25: v2(935.53,1200) 1110,1025.53 1110,941.02 1200,851.02 v2(1200,848.5)
  Bottom Layer w15: v2(1200,848.5) 1226.89,821.61 U1.16@1307.17,821.61
NetC25_1: C25.1 R14.1 R19.1 R22.2 U3.2 | length 328.7
  Bottom Layer w25: R19.1@2200,638.5 2200,571.5 C25.1@2201.5,570 ; U3.2@2207.4,507.24 2207.4,564.09 C25.1@2201.5,570 ; R22.2@2310,471.5 R14.1@2310,548.5 2308.5,550 2250,550 2230,570 C25.1@2201.5,570
NetC25_2: C25.2 C28.2 D18.1 R17.1 U2.2 U3.1 | length 828.7
  Top Layer w25: U2.2@1624.02,465 1630.51,471.5 R17.1@1690,471.5 1691.5,470 v2(1730,470)
  Bottom Layer w25: v2(1730,470) 1787.4,412.6 D18.1@1882.76,412.6 1937.4,412.6 1990,360 2110,360 2120,370 2120,470 2132.6,482.6 U3.1@2132.6,507.24 2132.6,564.09 C25.2@2138.5,570 2138.5,630 C28.2@2130,638.5
NetC26_1: C26.1 D18.3 R13.1 | length 202.3
  Bottom Layer w25: R13.1@1961.5,560 1977.24,544.25 D18.3@1977.24,450 2008.74,418.5 C26.1@2050,418.5
NetC28_1: C28.1 R19.2 | length 70
  Bottom Layer w25: C28.1@2130,701.5 R19.2@2200,701.5
NetC30_1: C30.1 R23.1 U1.15 | length 364
  Inner Layer 1 w15: v2(1180,680) v2(1180,796.02)
  Bottom Layer w15: C30.1@1130,848.5 1130,846.02 v2(1180,796.02) U1.15@1307.17,796.02 ; R23.1@1161.5,720 1161.5,698.5 v2(1180,680)
NetC31_2: C31.2 R27.2 | length 83.3
  Bottom Layer w15: R27.2@1620,668.5 1620,628.54 1630,618.54 1630,591.5 C31.2@1628.5,590
NetD11_1: D11.1 D12.2 Q1.4 R7.2 | length 256.5
  Top Layer w18: v2(1910,790) Q1.4@1910,820.59
  Bottom Layer w30: v2(1910,790) 1908.68,791.32 1908.68,898.68 1970,960 R7.2@1970,990
  other v2: 2090,1140 2090,1180
NetD11_2: D11.2 D13.2 | length 69.5
  Bottom Layer w30: D13.2@1983.31,1080 1990,1073.31 D11.2@2050,1073.31
NetD12_1: D12.1 R7.1 T2.6
  other v2: 1808.19,1058.19 1860,1150 1860,1190
NetD13_1: D13.1 D14.1 D14.2 Q1.1 Q1.2 Q1.3 R9.1 T2.7 | length 33.3
  Bottom Layer w30: D13.1@1896.69,1080 v2(1930,1080)
NetD15_2: D15.2 Q2.1 Q2.2 Q2.5 Q2.6 T2.1
NetD16_2: D16.2 R10.1 | length 111.9
  Top Layer w30: R10.1@1060,1130 1060,1235.53 D16.2@1064.47,1240
NetD17_1: D17.1 R11.1 U1.17 | length 542.7
  Inner Layer 1 w15: v2(1240,580) 1240,670 1211.12,698.88 1211.12,796.02 1250,834.9 v2(1250,860)
  Bottom Layer w15: R11.1@1178.31,583.82 1182.13,580 v2(1240,580) ; v2(1250,860) 1250,850 1252.8,847.2 U1.17@1307.17,847.2
  Bottom Layer w25: R11.1@1178.31,583.82 1178.31,508.29 D17.1@1197.78,488.82
NetD17_2: D17.2 Q2.3 R11.2 | length 252.6
  Top Layer w20: Q2.3@971.18,557.4 971.18,561.18 v1(1000,590)
  Bottom Layer w30: v1(1000,590) 1092.13,590 R11.2@1098.31,583.82 1098.31,518.29 D17.2@1068.84,488.82
NetD18_2: D18.2 R12.1 R13.2 R14.2 R15.2 TP3.1 | length 1363.7
  Top Layer w25: TP3.1@1540,250 1730,250 1830,350 v2(1830,470) 1781.5,470 R15.2@1780,471.5
  Inner Layer 1 w25: v2(1830,470) 2240,470 v2(2370,600)
  Bottom Layer w25: v2(1830,470) 1847.4,487.4 D18.2@1882.76,487.4 1898.5,503.15 R13.2@1898.5,560 ; R14.2@2310,611.5 2327.01,611.5 2350,588.5 ; v2(2370,600) 2358.5,588.5 2350,588.5 ; R12.1@2388.5,550 2350,588.5
NetJ1_1: J1.1 T1.1 | length 597.1
  Top Layer w25: T1.1@1577.51,1495.01 1704.99,1495.01 1740,1460 1960,1460 v2(2000,1500)
  Bottom Layer w25: v2(2000,1500) 2000,1587.24 J1.1@2039.84,1627.09
NetJ1_2: J1.2 T1.3 | length 557.2
  Top Layer w25: T1.3@1577.51,1595.01 1744.99,1595.01 1830,1510 1922.99,1510 1970,1557.01 J1.2@2080,1557.01
NetJ1_3: J1.3 T1.6 | length 738.7
  Top Layer w25: T1.6@1577.51,1745.01 1618.08,1745.01 1653.07,1780 1810,1780 1880,1850 2000,1850 2120.16,1729.84 J1.3@2120.16,1627.09
NetJ1_6: J1.6 T1.8 | length 1133.4
  Top Layer w25: T1.8@1577.51,1845.01 1580,1847.49 v2(1580,1890)
  Bottom Layer w25: v2(1580,1890) 1603.44,1866.56 1604.65,1866.56 1616.59,1854.63 1616.59,1853.41 1670,1800 1670,1510 1740,1440 2160,1440 2240.63,1520.63 J1.6@2240.63,1557.01
NetJ2_1: J2.1 T1.16 | length 1012.9
  Top Layer w25: J2.1@439.84,1627.09 432.99,1627.09 402.95,1597.05 402.95,1507.05 450,1460 1104.99,1460 1140,1495.01 T1.16@1242.51,1495.01
NetJ2_2: J2.2 T1.14 | length 853.1
  Top Layer w25: J2.2@480,1570 J2.2@480,1557.01 480,1532.01 512.01,1500 1021.02,1500 1116.03,1595.01 T1.14@1242.51,1595.01
NetJ2_3: J2.3 T1.11 | length 881
  Top Layer w25: J2.3@520.16,1627.09 520.16,1680.16 680,1840 900,1840 960,1780 1130,1780 1164.99,1745.01 T1.11@1242.51,1745.01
